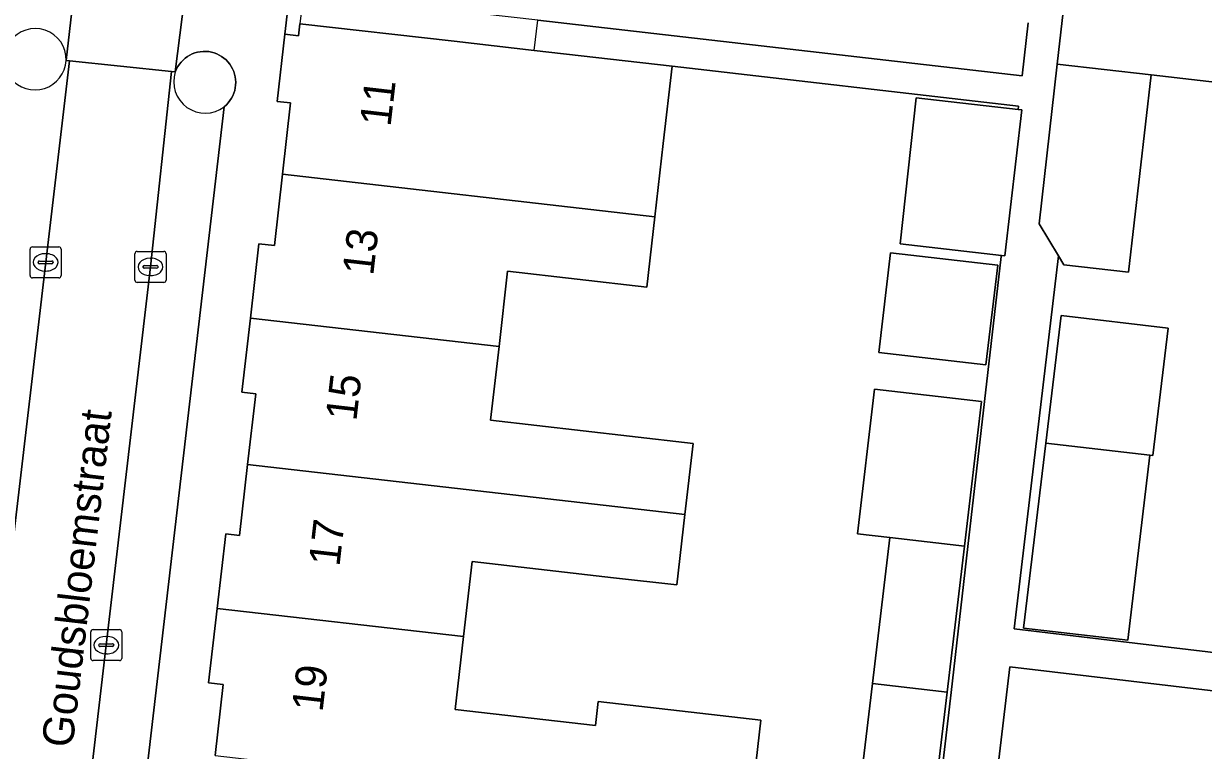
# Model space of a CAD drawing. Extents: x 161692 to 162379, y 380760 to 381678.
# Drawn here: x 162217.92 to 162255.9, y 381072.52 to 381095.93 of the extents above; entities that cross this region are included whole.
import ezdxf

# ---------------------------------------------------------------- set-up
doc = ezdxf.new("R2010")
doc.units = 0
for name, color, linetype in [('IMGEO_Erf', 7, 'Continuous'), ('IMGEO_Groenvoorziening', 7, 'Continuous'), ('IMGEO_Kolk', 7, 'Continuous'), ('IMGEO_Openbare_ruimte_label', 7, 'Continuous'), ('IMGEO_Pand', 7, 'Continuous'), ('IMGEO_Pand_nummerreeks', 7, 'Continuous'), ('IMGEO_Pand_overbouw', 7, 'Continuous'), ('IMGEO_Parkeervlak_open', 7, 'Continuous'), ('IMGEO_Rijbaan_lokaal_open', 7, 'Continuous'), ('IMGEO_Voetpad_open', 7, 'Continuous')]:
    doc.layers.add(name, color=color, linetype=linetype)

msp = doc.modelspace()

# ---------------------------------------------------------------- linework, layer by layer
at = {"layer": 'IMGEO_Erf'}
for points in [[(162259.521, 381115.117), (162257.099, 381093.948), (162254.216, 381094.277), (162253.491, 381087.922), (162251.412, 381088.16), (162251.239, 381088.444), (162249.813, 381076.434), (162264.901, 381074.642), (162265.333, 381078.414), (162263.281, 381078.649), (162263.545, 381080.955), (162263.81, 381083.27), (162264.252, 381087.031), (162264.651, 381090.42), (162264.905, 381092.634), (162265.312, 381092.587), (162265.662, 381095.63), (162258.747, 381096.421)], [(162234.472, 381096.038), (162250.064, 381094.242), (162250.261, 381095.954)], [(162247.237, 381069.698), (162247.777, 381074.382), (162248.318, 381079.082), (162249.394, 381088.427), (162249.398, 381088.461), (162246.143, 381088.834), (162246.657, 381093.542), (162249.94, 381093.166), (162249.952, 381093.269), (162238.797, 381094.554), (162238.512, 381092.062), (162238.242, 381089.703), (162237.983, 381087.443), (162233.501, 381087.955), (162233.224, 381085.532), (162232.952, 381083.153), (162237.43, 381082.641), (162239.471, 381082.408), (162239.21, 381080.118), (162238.95, 381077.847), (162236.908, 381078.08), (162232.36, 381078.6), (162232.084, 381076.182), (162231.815, 381073.834), (162236.327, 381073.318), (162236.411, 381074.092), (162241.65, 381073.494), (162241.294, 381070.377)], [(162262.757, 381073.661), (162249.668, 381075.215), (162247.52, 381057.127), (162246.249, 381046.311), (162245.475, 381039.702), (162244.896, 381034.012), (162244.259, 381027.764), (162243.52, 381021.774), (162246.411, 381021.417), (162260.68, 381019.761)]]:
    msp.add_lwpolyline(points, dxfattribs=at)
for points in [[(162245.451, 381085.334), (162245.826, 381088.547), (162249.282, 381088.151), (162248.901, 381084.94)], [(162254.767, 381086.114), (162254.277, 381082.021), (162254.183, 381082.032), (162253.469, 381076.074), (162250.115, 381076.46), (162250.828, 381082.418), (162251.32, 381086.526)], [(162245.313, 381084.153), (162248.761, 381083.759), (162248.207, 381079.093), (162247.65, 381074.397), (162247.094, 381069.716), (162244.689, 381070.001), (162245.244, 381074.673), (162245.803, 381079.375), (162244.769, 381079.496)]]:
    msp.add_lwpolyline(points, close=True, dxfattribs=at)
at = {"layer": 'IMGEO_Groenvoorziening'}
msp.add_lwpolyline([(162224.378, 381093.251), (162224.445, 381093.311), (162224.506, 381093.376), (162224.562, 381093.447), (162224.61, 381093.522), (162224.652, 381093.602), (162224.687, 381093.685), (162224.714, 381093.77), (162224.733, 381093.858), (162224.744, 381093.947), (162224.748, 381094.037), (162224.743, 381094.126), (162224.73, 381094.215), (162224.71, 381094.303), (162224.682, 381094.388), (162224.646, 381094.47), (162224.603, 381094.549), (162224.553, 381094.624), (162224.497, 381094.694), (162224.434, 381094.758), (162224.366, 381094.817), (162224.293, 381094.87), (162224.216, 381094.915), (162224.135, 381094.954), (162224.051, 381094.985), (162223.964, 381095.009), (162223.876, 381095.025), (162223.787, 381095.032), (162223.697, 381095.032), (162223.607, 381095.024), (162223.519, 381095.008), (162223.433, 381094.984), (162223.349, 381094.952), (162223.268, 381094.913), (162223.191, 381094.867), (162223.118, 381094.814), (162223.05, 381094.755), (162222.988, 381094.691), (162222.932, 381094.62), (162222.883, 381094.546), (162222.84, 381094.467), (162222.804, 381094.384), (162222.8, 381094.372)], dxfattribs=at)
for centre, radius, start, end in [((162218.291, 381094.77), 0.999, 358.3478, 217.0604), ((162218.281, 381094.8), 1.009, 218.7407, 356.6676), ((162223.764, 381094.058), 1.014, 161.9404, 307.2802)]:
    msp.add_arc(centre, radius, start, end, dxfattribs=at)
at = {"layer": 'IMGEO_Kolk'}
for p, q in [((162218.125, 381087.812), (162218.125, 381088.664)), ((162218.2, 381088.738), (162219.052, 381088.738)), ((162218.613, 381088.518), (162218.638, 381088.518)), ((162219.126, 381088.664), (162219.126, 381087.812)), ((162221.502, 381087.665), (162221.502, 381088.517)), ((162221.577, 381088.591), (162222.429, 381088.591)), ((162222.503, 381088.517), (162222.503, 381087.665)), ((162218.384, 381088.232), (162218.384, 381088.244)), ((162218.822, 381088.195), (162218.424, 381088.195)), ((162218.427, 381088.281), (162218.825, 381088.281)), ((162218.868, 381088.244), (162218.868, 381088.232)), ((162221.761, 381088.085), (162221.761, 381088.097)), ((162221.804, 381088.134), (162222.202, 381088.134)), ((162221.99, 381088.371), (162222.015, 381088.371)), ((162222.245, 381088.097), (162222.245, 381088.085)), ((162219.052, 381087.738), (162218.2, 381087.738)), ((162218.636, 381087.958), (162218.611, 381087.958)), ((162222.199, 381088.048), (162221.801, 381088.048)), ((162222.013, 381087.811), (162221.988, 381087.811)), ((162222.429, 381087.591), (162221.577, 381087.591)), ((162220.079, 381075.483), (162220.079, 381076.335)), ((162220.154, 381076.409), (162221.006, 381076.409)), ((162221.08, 381076.335), (162221.08, 381075.483)), ((162220.381, 381075.952), (162220.779, 381075.952)), ((162220.567, 381076.189), (162220.592, 381076.189)), ((162220.338, 381075.903), (162220.338, 381075.915)), ((162220.776, 381075.866), (162220.378, 381075.866)), ((162220.59, 381075.629), (162220.565, 381075.629)), ((162220.822, 381075.915), (162220.822, 381075.903)), ((162221.006, 381075.409), (162220.154, 381075.409))]:
    msp.add_line(p, q, dxfattribs=at)
for points in [[(162218.125, 381087.812), (162218.125, 381088.664)], [(162218.2, 381088.738), (162219.052, 381088.738)], [(162219.126, 381088.664), (162219.126, 381087.812)], [(162221.502, 381087.665), (162221.502, 381088.517)], [(162221.577, 381088.591), (162222.429, 381088.591)], [(162222.503, 381088.517), (162222.503, 381087.665)], [(162219.052, 381087.738), (162218.2, 381087.738)], [(162222.429, 381087.591), (162221.577, 381087.591)], [(162220.079, 381075.483), (162220.079, 381076.335)], [(162220.154, 381076.409), (162221.006, 381076.409)], [(162221.08, 381076.335), (162221.08, 381075.483)], [(162221.006, 381075.409), (162220.154, 381075.409)]]:
    msp.add_lwpolyline(points, dxfattribs=at)
for centre, radius, start, end in [((162218.202, 381088.662), 0.0765, 91.552, 178.448), ((162218.202, 381088.662), 0.0765, 91.552, 178.448), ((162219.05, 381088.662), 0.0765, 1.552, 88.448), ((162219.05, 381088.662), 0.0765, 1.552, 88.448), ((162221.579, 381088.515), 0.0765, 91.552, 178.448), ((162221.579, 381088.515), 0.0765, 91.552, 178.448), ((162222.427, 381088.515), 0.0765, 1.552, 88.448), ((162222.427, 381088.515), 0.0765, 1.552, 88.448), ((162218.424, 381088.241), 0.0403, 85.8775, 175.7526), ((162218.421, 381088.231), 0.0366, 178.938, 274.7102), ((162218.825, 381088.238), 0.043, 264.8664, 352.4533), ((162218.829, 381088.243), 0.0386, 1.7309, 96.639), ((162221.801, 381088.094), 0.0403, 85.8775, 175.7526), ((162222.206, 381088.096), 0.0386, 1.7309, 96.639), ((162218.202, 381087.814), 0.0765, 181.552, 268.448), ((162218.202, 381087.814), 0.0765, 181.552, 268.448), ((162219.05, 381087.814), 0.0765, 271.552, 358.448), ((162219.05, 381087.814), 0.0765, 271.552, 358.448), ((162221.798, 381088.084), 0.0366, 178.938, 274.7102), ((162222.202, 381088.091), 0.043, 264.8664, 352.4533), ((162221.579, 381087.667), 0.0765, 181.552, 268.448), ((162221.579, 381087.667), 0.0765, 181.552, 268.448), ((162222.427, 381087.667), 0.0765, 271.552, 358.448), ((162222.427, 381087.667), 0.0765, 271.552, 358.448), ((162220.156, 381076.333), 0.0765, 91.552, 178.448), ((162220.156, 381076.333), 0.0765, 91.552, 178.448), ((162221.004, 381076.333), 0.0765, 1.552, 88.448), ((162221.004, 381076.333), 0.0765, 1.552, 88.448), ((162220.378, 381075.912), 0.0403, 85.8775, 175.7526), ((162220.783, 381075.914), 0.0386, 1.7309, 96.639), ((162220.375, 381075.902), 0.0366, 178.938, 274.7102), ((162220.779, 381075.909), 0.043, 264.8664, 352.4533), ((162220.156, 381075.485), 0.0765, 181.552, 268.448), ((162220.156, 381075.485), 0.0765, 181.552, 268.448), ((162221.004, 381075.485), 0.0765, 271.552, 358.448), ((162221.004, 381075.485), 0.0765, 271.552, 358.448)]:
    msp.add_arc(centre, radius, start, end, dxfattribs=at)
for centre, major_axis, ratio, start_param, end_param in [((162218.612, 381088.238), (-0.387, 0.002), 0.722429, 4.712389, 7.853982), ((162218.637, 381088.238), (-0.39, 0.002), 0.717154, 1.570796, 4.712389), ((162221.989, 381088.091), (-0.387, 0.002), 0.722429, 4.712389, 7.853982), ((162222.014, 381088.091), (-0.39, 0.002), 0.717154, 1.570796, 4.712389), ((162220.566, 381075.909), (-0.387, 0.002), 0.722429, 4.712389, 7.853982), ((162220.591, 381075.909), (-0.39, 0.002), 0.717154, 1.570796, 4.712389)]:
    msp.add_ellipse(centre, major_axis=major_axis, ratio=ratio, start_param=start_param, end_param=end_param, dxfattribs=at)
at = {"layer": 'IMGEO_Pand'}
for points in [[(162259.521, 381115.117), (162259.659, 381115.101), (162259.782, 381116.18), (162260.051, 381118.526), (162260.619, 381123.493), (162254.577, 381124.184), (162254.009, 381119.217), (162253.252, 381112.593), (162251.241, 381095), (162251.198, 381094.622), (162254.216, 381094.277), (162257.099, 381093.948)], [(162226.252, 381091.075), (162238.242, 381089.703), (162238.512, 381092.062), (162238.797, 381094.554), (162234.357, 381095.063), (162231.782, 381095.358), (162226.814, 381095.926), (162226.769, 381095.534), (162226.328, 381095.584), (162226.081, 381093.422), (162226.515, 381093.372)], [(162254.216, 381094.277), (162251.198, 381094.622), (162250.61, 381089.48), (162251.239, 381088.444), (162251.412, 381088.16), (162253.491, 381087.922)], [(162249.94, 381093.166), (162246.657, 381093.542), (162246.143, 381088.834), (162249.398, 381088.461), (162249.513, 381088.448), (162250.052, 381093.153)], [(162226.252, 381091.075), (162225.99, 381088.778), (162225.495, 381088.834), (162225.222, 381086.445), (162233.224, 381085.532), (162233.501, 381087.955), (162237.983, 381087.443), (162238.242, 381089.703)], [(162245.451, 381085.334), (162248.901, 381084.94), (162249.282, 381088.151), (162245.826, 381088.547)], [(162239.21, 381080.118), (162239.471, 381082.408), (162237.43, 381082.641), (162232.952, 381083.153), (162233.224, 381085.532), (162225.222, 381086.445), (162224.948, 381084.055), (162225.391, 381084.004), (162225.13, 381081.722)], [(162254.767, 381086.114), (162251.32, 381086.526), (162250.828, 381082.418), (162254.183, 381082.032), (162254.277, 381082.021)], [(162245.313, 381084.153), (162244.769, 381079.496), (162245.803, 381079.375), (162246.09, 381079.342), (162248.207, 381079.093), (162248.761, 381083.759)], [(162254.183, 381082.032), (162250.828, 381082.418), (162250.115, 381076.46), (162253.469, 381076.074)], [(162239.21, 381080.118), (162225.13, 381081.722), (162224.869, 381079.439), (162224.423, 381079.49), (162224.148, 381077.092), (162232.084, 381076.182), (162232.36, 381078.6), (162236.908, 381078.08), (162238.95, 381077.847)], [(162248.207, 381079.093), (162246.09, 381079.342), (162245.803, 381079.375), (162245.244, 381074.673), (162245.531, 381074.639), (162247.65, 381074.397)], [(162224.082, 381072.35), (162241.294, 381070.377), (162241.65, 381073.494), (162236.411, 381074.092), (162236.327, 381073.318), (162231.815, 381073.834), (162232.084, 381076.182), (162224.148, 381077.092), (162223.874, 381074.696), (162224.344, 381074.642)], [(162247.65, 381074.397), (162245.531, 381074.639), (162245.244, 381074.673), (162244.689, 381070.001), (162247.094, 381069.716)]]:
    msp.add_lwpolyline(points, close=True, dxfattribs=at)
at = {"layer": 'IMGEO_Pand_overbouw'}
msp.add_lwpolyline([(162226.814, 381095.926), (162231.782, 381095.358), (162234.357, 381095.063), (162234.472, 381096.038), (162226.926, 381096.901)], close=True, dxfattribs=at)
at = {"layer": 'IMGEO_Parkeervlak_open'}
for points in [[(162214.64, 381056.476), (162214.924, 381056.471), (162215.568, 381062.131), (162217.21, 381076.083), (162218.628, 381088.239), (162219.396, 381094.73), (162219.289, 381094.741)], [(162222.8, 381094.372), (162222.682, 381094.384), (162222.002, 381088.091), (162220.579, 381075.909), (162218.907, 381061.654), (162218.219, 381056.054), (162218.512, 381056.025)], [(162220.162, 381057.055), (162224.378, 381093.251)]]:
    msp.add_lwpolyline(points, dxfattribs=at)
for centre, radius, start, end in [((162218.281, 381094.8), 1.009, 218.7407, 356.6676), ((162223.764, 381094.058), 1.014, 161.9404, 307.2802)]:
    msp.add_arc(centre, radius, start, end, dxfattribs=at)
at = {"layer": 'IMGEO_Rijbaan_lokaal_open'}
for points in [[(162223.318, 381098.518), (162223.186, 381098.538), (162219.859, 381098.874), (162219.759, 381098.862), (162219.289, 381094.741), (162219.396, 381094.73), (162222.682, 381094.384), (162222.8, 381094.372)], [(162219.396, 381094.73), (162218.628, 381088.239), (162217.21, 381076.083), (162215.568, 381062.131), (162214.924, 381056.471), (162218.219, 381056.054), (162218.907, 381061.654), (162220.579, 381075.909), (162222.002, 381088.091), (162222.682, 381094.384)]]:
    msp.add_lwpolyline(points, close=True, dxfattribs=at)
at = {"layer": 'IMGEO_Voetpad_open'}
for points in [[(162264.901, 381074.642), (162249.813, 381076.434), (162251.239, 381088.444), (162250.61, 381089.48), (162251.198, 381094.622), (162251.241, 381095), (162253.252, 381112.593)], [(162219.289, 381094.741), (162219.759, 381098.862)], [(162223.318, 381098.518), (162222.8, 381094.372), (162222.804, 381094.384), (162222.84, 381094.467), (162222.883, 381094.546), (162222.932, 381094.62), (162222.988, 381094.691), (162223.05, 381094.755), (162223.118, 381094.814), (162223.191, 381094.867), (162223.268, 381094.913), (162223.349, 381094.952), (162223.433, 381094.984), (162223.519, 381095.008), (162223.607, 381095.024), (162223.697, 381095.032), (162223.787, 381095.032), (162223.876, 381095.025), (162223.964, 381095.009), (162224.051, 381094.985), (162224.135, 381094.954), (162224.216, 381094.915), (162224.293, 381094.87), (162224.366, 381094.817), (162224.434, 381094.758), (162224.497, 381094.694), (162224.553, 381094.624), (162224.603, 381094.549), (162224.646, 381094.47), (162224.682, 381094.388), (162224.71, 381094.303), (162224.73, 381094.215), (162224.743, 381094.126), (162224.748, 381094.037), (162224.744, 381093.947), (162224.733, 381093.858), (162224.714, 381093.77), (162224.687, 381093.685), (162224.652, 381093.602), (162224.61, 381093.522), (162224.562, 381093.447), (162224.506, 381093.376), (162224.445, 381093.311), (162224.378, 381093.251), (162220.162, 381057.055)], [(162224.082, 381072.35), (162224.344, 381074.642), (162223.874, 381074.696), (162224.148, 381077.092), (162224.423, 381079.49), (162224.869, 381079.439), (162225.13, 381081.722), (162225.391, 381084.004), (162224.948, 381084.055), (162225.222, 381086.445), (162225.495, 381088.834), (162225.99, 381088.778), (162226.252, 381091.075), (162226.515, 381093.372), (162226.081, 381093.422), (162226.328, 381095.584), (162226.496, 381097.065)], [(162226.496, 381097.065), (162226.328, 381095.584), (162226.769, 381095.534), (162226.814, 381095.926), (162231.782, 381095.358), (162234.357, 381095.063), (162238.797, 381094.554), (162249.952, 381093.269), (162249.94, 381093.166), (162250.052, 381093.153), (162249.513, 381088.448), (162249.398, 381088.461), (162249.394, 381088.427), (162248.318, 381079.082), (162247.777, 381074.382), (162247.237, 381069.698)], [(162250.261, 381095.954), (162250.064, 381094.242), (162234.472, 381096.038)], [(162260.68, 381019.761), (162246.411, 381021.417), (162243.52, 381021.774), (162244.259, 381027.764), (162244.896, 381034.012), (162245.475, 381039.702), (162246.249, 381046.311), (162247.52, 381057.127), (162249.668, 381075.215), (162262.757, 381073.661)]]:
    msp.add_lwpolyline(points, dxfattribs=at)
msp.add_arc((162218.291, 381094.77), 0.999, 358.3478, 217.0604, dxfattribs=at)

# ---------------------------------------------------------------- texts
at = {"layer": 'IMGEO_Openbare_ruimte_label'}
msp.add_text('Goudsbloemstraat', height=1, rotation=83.337, dxfattribs=at).set_placement((162219.489, 381072.578))
at = {"layer": 'IMGEO_Pand_nummerreeks'}
for s, p in [('11', (162229.729, 381092.588)), ('13', (162229.172, 381087.79)), ('15', (162228.629, 381083.105)), ('17', (162228.085, 381078.42)), ('19', (162227.541, 381073.734))]:
    msp.add_text(s, height=1, rotation=83.381, dxfattribs=at).set_placement(p)

doc.saveas('drawing.dxf')
